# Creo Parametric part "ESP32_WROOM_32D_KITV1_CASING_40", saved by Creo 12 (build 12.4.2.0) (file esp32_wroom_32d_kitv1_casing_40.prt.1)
Units: Custom; MM, KILOGRAM, SECS

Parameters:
  PTC_WM_ITERATION = "0"
  PTC_WM_VERSION = "-.0"
  PTC_WM_LIFECYCLE_STATE = "In Work"
  PTC_WM_LIFECYCLE = "MO_CADDocument"
  PTC_WM_CREATED_BY = "Maximilian Roepper (Z0017RMS: MO)"
  PTC_WM_CREATED_ON = "18-Sep-26 11:36:42 AM"
  PTC_WM_MODIFIED_BY = "Maximilian Roepper (Z0017RMS: MO)"
  PTC_WM_MODIFIED_ON = "18-Sep-26 11:36:46 AM"
  PDMLINKNUMBER = "PDM000071455111"
  PTC_WM_NAME = "esp32_wroom_32d_kitv1_casing_40.prt"
  PTC_WM_NUMBER = "PDM000071455111"

Other parameters: WEIGHT, WEIGHT_FACTOR, WEIGHT_ADD, _MASS_TEMP, _DIFF_TEMP, MC_ERRORS, SUPPLIER

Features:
  1. coordinate system
  2. datum plane "PRT_YZ"
  3. datum plane "PRT_XY"
  4. datum plane "PRT_XZ"
  5. coordinate system
  6. datum axis
  7. datum axis
  8. datum axis
  9. coordinate system
  10. imported feature
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
Other named items: PRT, SIEMENS_MO, DRW_VIEW_ORG, PRT_X, PRT_Y, PRT_Z, CS0, ROUGH_GROB

Layers: 00_STD_CSYS-KSYS, 01_STD_PLANES-EBENEN, 02_STD_AXES-ACHSEN, 03_STD_CSYS-KSYS, 24_IMPORT_FEAT-IMPORT_KE

Surfaces: 5 plane, 1 cylinder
